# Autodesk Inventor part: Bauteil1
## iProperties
Created: 2010-04
Part Number: Bauteil1
Document SubType Name: Modeling
Designer: Administrator
Density: 1 g/cm^3
Author: Administrator
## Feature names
1. Extrusion1
